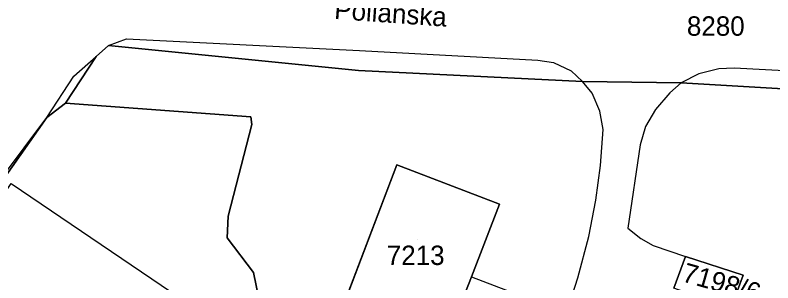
# Model space of a CAD drawing. Extents: x -266199 to -261993, y -1239047 to -1235108.
# Drawn here: x -263650.7 to -263572.7, y -1236492.8 to -1236465.2 of the extents above; entities that cross this region are included whole.
import ezdxf

# ---------------------------------------------------------------- set-up
doc = ezdxf.new("R2010")
doc.units = 0
for name, color, linetype in [('body_kn', 7, 'Continuous'), ('kladpar_druhypozemkov', 7, 'Continuous'), ('kladpar_hranice', 7, 'Continuous'), ('kladpar_parcelnecisla', 7, 'Continuous'), ('kladpar_plochy', 7, 'Continuous'), ('popisy', 7, 'Continuous'), ('zappar_hrandruhpozemk', 7, 'Continuous')]:
    doc.layers.add(name, color=color, linetype=linetype)

msp = doc.modelspace()

# ---------------------------------------------------------------- linework, layer by layer
at = {"layer": 'body_kn'}
for p, q in [((-263641.09, -1236468.33), (-263641.09, -1236468.33)), ((-263641.09, -1236468.33), (-263641.09, -1236468.33)), ((-263639.23, -1236467.62), (-263639.23, -1236467.62)), ((-263615.22, -1236468.84), (-263615.22, -1236468.84)), ((-263642.36, -1236469.45), (-263642.36, -1236469.45)), ((-263596.87, -1236469.82), (-263596.87, -1236469.82)), ((-263595.26, -1236470.06), (-263595.26, -1236470.06)), ((-263576.66, -1236470.66), (-263576.66, -1236470.66)), ((-263644.64, -1236471.48), (-263644.64, -1236471.48)), ((-263615.33, -1236470.89), (-263615.33, -1236470.89)), ((-263593.44, -1236470.94), (-263593.44, -1236470.94)), ((-263580.29, -1236471.25), (-263580.29, -1236471.25)), ((-263578.23, -1236470.74), (-263578.23, -1236470.74)), ((-263592.26, -1236472.04), (-263592.26, -1236472.04)), ((-263582.09, -1236472.17), (-263582.09, -1236472.17)), ((-263582.09, -1236472.17), (-263582.09, -1236472.17)), ((-263591.28, -1236473.24), (-263591.28, -1236473.24)), ((-263583.27, -1236473.19), (-263583.27, -1236473.19)), ((-263645.5, -1236474.26), (-263645.5, -1236474.26)), ((-263645.5, -1236474.26), (-263645.5, -1236474.26)), ((-263590.47, -1236475.09), (-263590.47, -1236475.09)), ((-263584.76, -1236474.92), (-263584.76, -1236474.92)), ((-263647.44, -1236475.73), (-263647.44, -1236475.73)), ((-263626.44, -1236475.66), (-263626.44, -1236475.66)), ((-263626.33, -1236476.45), (-263626.33, -1236476.45)), ((-263585.79, -1236476.69), (-263585.79, -1236476.69)), ((-263590.13, -1236477), (-263590.13, -1236477)), ((-263586.32, -1236478.57), (-263586.32, -1236478.57)), ((-263611.39, -1236480.64), (-263611.39, -1236480.64)), ((-263590.4, -1236480.69), (-263590.4, -1236480.69)), ((-263600.8, -1236484.67), (-263600.8, -1236484.67)), ((-263590.89, -1236484.28), (-263590.89, -1236484.28)), ((-263628.77, -1236485.94), (-263628.77, -1236485.94)), ((-263587.58, -1236487.15), (-263587.58, -1236487.15)), ((-263628.88, -1236488.15), (-263628.88, -1236488.15)), ((-263591.6, -1236488.03), (-263591.6, -1236488.03)), ((-263586.27, -1236488.22), (-263586.27, -1236488.22)), ((-263584.99, -1236488.94), (-263584.99, -1236488.94)), ((-263581.67, -1236490.07), (-263581.67, -1236490.07)), ((-263626.15, -1236491.73), (-263626.15, -1236491.73)), ((-263603.7, -1236492.17), (-263603.7, -1236492.17)), ((-263603.7, -1236492.17), (-263603.7, -1236492.17)), ((-263592.75, -1236492.27), (-263592.75, -1236492.27)), ((-263575.73, -1236492.02), (-263575.73, -1236492.02))]:
    msp.add_line(p, q, dxfattribs=at)
at = {"layer": 'kladpar_druhypozemkov'}
for p, q in [((-263609.29, -1236488.36), (-263609.29, -1236488.36)), ((-263579.16, -1236491.56), (-263579.16, -1236491.56))]:
    msp.add_line(p, q, dxfattribs=at)
at = {"layer": 'kladpar_hranice'}
for points in [[(-263524.5, -1236462.92), (-263525.44, -1236474.41), (-263525.13, -1236478.12), (-263525.75, -1236476.92), (-263527.31, -1236475.67), (-263529.4, -1236475.19), (-263532.17, -1236474.97), (-263554.68, -1236473.85), (-263559.32, -1236473.51), (-263582.09, -1236472.17), (-263592.26, -1236472.04), (-263615.33, -1236470.89), (-263641.09, -1236468.33), (-263642.36, -1236469.45), (-263645.5, -1236474.26), (-263647.44, -1236475.73), (-263651.91, -1236482.11), (-263652.12, -1236482.01), (-263655.84, -1236479.78), (-263656.07, -1236479.6), (-263653.26, -1236475.65), (-263655, -1236473.5)], [(-263645.5, -1236474.26), (-263642.36, -1236469.45), (-263641.09, -1236468.33), (-263615.33, -1236470.89), (-263592.26, -1236472.04), (-263582.09, -1236472.17), (-263559.32, -1236473.51), (-263554.68, -1236473.85), (-263532.17, -1236474.97), (-263529.4, -1236475.19), (-263527.31, -1236475.67), (-263525.75, -1236476.92), (-263525.13, -1236478.12), (-263525.16, -1236480.27), (-263525.8, -1236491.06), (-263525.84, -1236494.32), (-263526.69, -1236510.66), (-263527.03, -1236513.3), (-263527.74, -1236530.38), (-263528.13, -1236533.75), (-263528.91, -1236547.91)], [(-263745.77, -1236505), (-263720.79, -1236469.94), (-263655, -1236473.5), (-263653.26, -1236475.65), (-263656.07, -1236479.6), (-263655.84, -1236479.78), (-263652.12, -1236482.01), (-263651.91, -1236482.11), (-263647.44, -1236475.73), (-263645.5, -1236474.26), (-263626.44, -1236475.66), (-263626.33, -1236476.45), (-263628.77, -1236485.94), (-263628.88, -1236488.15), (-263626.15, -1236491.73), (-263625.65, -1236494.26), (-263634.41, -1236515.37), (-263635.09, -1236517.76), (-263650.28, -1236558.18), (-263636.73, -1236565.67), (-263652.65, -1236609.13)], [(-263652.65, -1236609.13), (-263636.73, -1236565.67), (-263650.28, -1236558.18), (-263635.09, -1236517.76), (-263634.41, -1236515.37), (-263625.65, -1236494.26), (-263626.15, -1236491.73), (-263628.88, -1236488.15), (-263628.77, -1236485.94), (-263626.33, -1236476.45), (-263626.44, -1236475.66), (-263645.5, -1236474.26)], [(-263611.39, -1236480.64), (-263617.27, -1236496.08), (-263624.38, -1236514.77), (-263631.43, -1236533.27), (-263632.4, -1236535.87), (-263633.34, -1236538.4), (-263634.3, -1236540.96), (-263635.24, -1236543.48), (-263636.19, -1236546.03)], [(-263631.33, -1236547.93), (-263630.37, -1236545.41), (-263629.41, -1236542.87), (-263628.45, -1236540.33), (-263627.48, -1236537.79), (-263626.49, -1236535.16), (-263620.94, -1236537.26), (-263618.12, -1236529.89), (-263617.46, -1236528.15), (-263613.87, -1236518.77), (-263611.28, -1236511.99), (-263610.57, -1236510.14), (-263606.72, -1236500.09), (-263604.37, -1236493.93), (-263603.7, -1236492.17), (-263600.8, -1236484.67), (-263611.39, -1236480.64)], [(-263617.27, -1236496.08), (-263611.39, -1236480.64), (-263600.8, -1236484.67), (-263603.7, -1236492.17), (-263604.37, -1236493.93), (-263606.72, -1236500.09)], [(-263582.87, -1236493.34), (-263581.67, -1236490.07), (-263575.73, -1236492.02), (-263576.98, -1236495.45), (-263582.87, -1236493.34)], [(-263576.98, -1236495.45), (-263575.73, -1236492.02), (-263581.67, -1236490.07), (-263582.87, -1236493.34)]]:
    msp.add_lwpolyline(points, dxfattribs=at)
at = {"layer": 'kladpar_plochy'}
for p, q in [((-263642.36, -1236469.45), (-263641.09, -1236468.33)), ((-263641.09, -1236468.33), (-263615.33, -1236470.89)), ((-263645.5, -1236474.26), (-263642.36, -1236469.45)), ((-263615.33, -1236470.89), (-263592.26, -1236472.04)), ((-263592.26, -1236472.04), (-263582.09, -1236472.17)), ((-263582.09, -1236472.17), (-263559.32, -1236473.51)), ((-263626.44, -1236475.66), (-263645.5, -1236474.26)), ((-263626.33, -1236476.45), (-263626.44, -1236475.66)), ((-263628.77, -1236485.94), (-263626.33, -1236476.45)), ((-263611.39, -1236480.64), (-263617.27, -1236496.08)), ((-263600.8, -1236484.67), (-263611.39, -1236480.64)), ((-263603.7, -1236492.17), (-263600.8, -1236484.67)), ((-263628.88, -1236488.15), (-263628.77, -1236485.94)), ((-263626.15, -1236491.73), (-263628.88, -1236488.15)), ((-263581.67, -1236490.07), (-263582.87, -1236493.34)), ((-263575.73, -1236492.02), (-263581.67, -1236490.07)), ((-263625.65, -1236494.26), (-263626.15, -1236491.73)), ((-263604.37, -1236493.93), (-263603.7, -1236492.17)), ((-263576.98, -1236495.45), (-263575.73, -1236492.02))]:
    msp.add_line(p, q, dxfattribs=at)
for points in [[(-263524.5, -1236462.92), (-263525.44, -1236474.41), (-263525.13, -1236478.12), (-263525.75, -1236476.92), (-263527.31, -1236475.67), (-263529.4, -1236475.19), (-263532.17, -1236474.97), (-263554.68, -1236473.85), (-263559.32, -1236473.51), (-263582.09, -1236472.17), (-263592.26, -1236472.04), (-263615.33, -1236470.89), (-263641.09, -1236468.33), (-263642.36, -1236469.45), (-263645.5, -1236474.26), (-263647.44, -1236475.73), (-263651.91, -1236482.11)], [(-263745.77, -1236505), (-263720.79, -1236469.94), (-263655, -1236473.5), (-263653.26, -1236475.65), (-263656.07, -1236479.6), (-263655.84, -1236479.78), (-263652.12, -1236482.01), (-263651.91, -1236482.11), (-263647.44, -1236475.73), (-263645.5, -1236474.26), (-263626.44, -1236475.66), (-263626.33, -1236476.45), (-263628.77, -1236485.94), (-263628.88, -1236488.15), (-263626.15, -1236491.73), (-263625.65, -1236494.26), (-263634.41, -1236515.37), (-263635.09, -1236517.76), (-263650.28, -1236558.18), (-263636.73, -1236565.67), (-263652.65, -1236609.13)]]:
    msp.add_lwpolyline(points, dxfattribs=at)
for points in [[(-263617.27, -1236496.08), (-263611.39, -1236480.64), (-263600.8, -1236484.67), (-263603.7, -1236492.17), (-263604.37, -1236493.93), (-263606.72, -1236500.09)], [(-263582.87, -1236493.34), (-263581.67, -1236490.07), (-263575.73, -1236492.02), (-263576.98, -1236495.45)]]:
    msp.add_lwpolyline(points, close=True, dxfattribs=at)
at = {"layer": 'zappar_hrandruhpozemk'}
for p, q in [((-263615.22, -1236468.84), (-263596.87, -1236469.82)), ((-263644.64, -1236471.48), (-263642.36, -1236469.45)), ((-263586.32, -1236478.57), (-263587.58, -1236487.15)), ((-263591.6, -1236488.03), (-263590.89, -1236484.28))]:
    msp.add_line(p, q, dxfattribs=at)
for points in [[(-263641.09, -1236468.33), (-263639.23, -1236467.62), (-263615.22, -1236468.84)], [(-263596.87, -1236469.82), (-263595.26, -1236470.06), (-263593.44, -1236470.94), (-263592.26, -1236472.04)], [(-263554.7, -1236471.84), (-263576.66, -1236470.66), (-263578.23, -1236470.74), (-263580.29, -1236471.25), (-263582.09, -1236472.17)], [(-263652.12, -1236482.01), (-263647.44, -1236475.73), (-263644.64, -1236471.48)], [(-263590.89, -1236484.28), (-263590.4, -1236480.69), (-263590.13, -1236477), (-263590.47, -1236475.09), (-263591.28, -1236473.24), (-263592.26, -1236472.04)], [(-263582.09, -1236472.17), (-263583.27, -1236473.19), (-263584.76, -1236474.92), (-263585.79, -1236476.69), (-263586.32, -1236478.57)], [(-263660.65, -1236539.21), (-263679.97, -1236525.75), (-263651.12, -1236482.57), (-263631.52, -1236495.85)], [(-263587.58, -1236487.15), (-263586.27, -1236488.22), (-263584.99, -1236488.94), (-263581.67, -1236490.07)], [(-263603.7, -1236492.17), (-263593.93, -1236495.93), (-263592.75, -1236492.27), (-263591.6, -1236488.03)]]:
    msp.add_lwpolyline(points, dxfattribs=at)

# ---------------------------------------------------------------- texts
at = {"layer": 'kladpar_parcelnecisla'}
for s, p in [('8280', (-263581.511, -1236467.31)), ('7213', (-263612.422, -1236490.96))]:
    msp.add_text(s, height=2, dxfattribs=at).set_placement(p)
msp.add_text('7198/6', height=2, rotation=344, dxfattribs=at).set_placement((-263582.119, -1236492.622))
at = {"layer": 'popisy'}
msp.add_text('Polianska', height=2, rotation=356, dxfattribs=at).set_placement((-263617.877, -1236465.57))

doc.saveas('drawing.dxf')
